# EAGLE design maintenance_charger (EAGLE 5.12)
TP_SIGNAL_NAME: REF
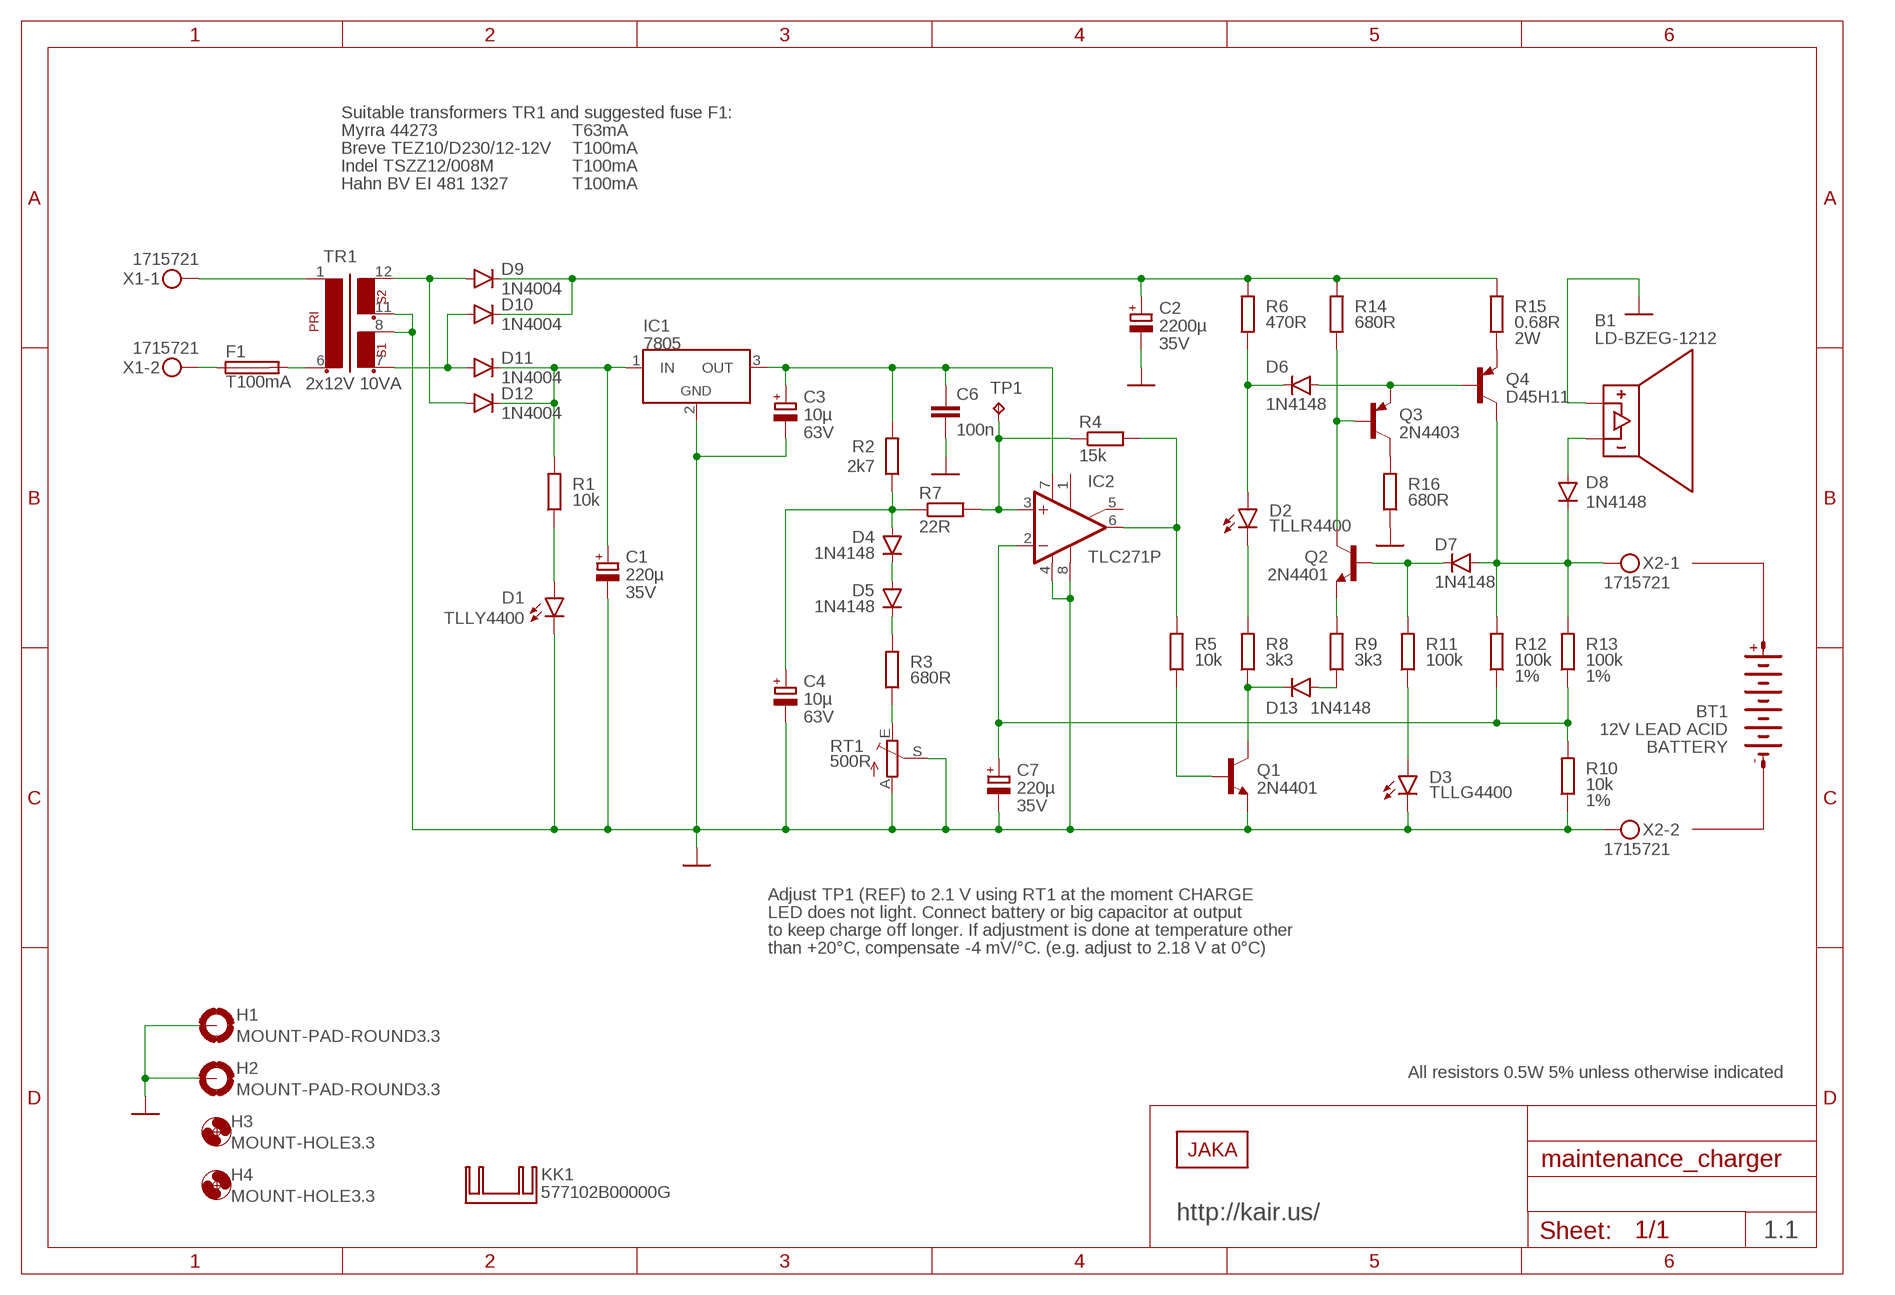
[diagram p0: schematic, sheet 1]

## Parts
B1  LD-BZEG-1212  [LD-BZEG-1212]
C1  220µ  CPOL-EUE3.5-8  [E3,5-8]
C2  2200µ  CPOL-EUE7.5-16  [E7,5-16]
C3  10µ  CPOL-EUE2-5  [E2-5]
C4  10µ  CPOL-EUE2-5  [E2-5]
C6  100n  C-EU050-025X075  [C050-025X075]
C7  220µ  CPOL-EUE3.5-8  [E3,5-8]
D1  TLLY4400  [LED3MM]
D2  TLLR4400  [LED3MM]
D3  TLLG4400  [LED3MM]
D4  1N4148  [DO35-10]
D5  1N4148  [DO35-10]
D6  1N4148  [DO35-10]
D7  1N4148  [DO35-10]
D8  1N4148  [DO35-10]
D9  1N4004  [DO41-10]
D10  1N4004  [DO41-10]
D11  1N4004  [DO41-10]
D12  1N4004  [DO41-10]
D13  1N4148  [DO35-10]
F1  T100mA  TR5  [TR5]
H1  MOUNT-PAD-ROUND3.3  [3,3-PAD]
H2  MOUNT-PAD-ROUND3.3  [3,3-PAD]
H3  MOUNT-HOLE3.3  [3,3]
H4  MOUNT-HOLE3.3  [3,3]
IC1  7805  7805V  [TO220V]
IC2  TLC271P  [DIL08]
KK1  577102B00000G  TO220_HEATSINK  [577102B00000G]
Q1  2N4401  2N4401-NPN-TO92-EBC  [TO92-EBC]
Q2  2N4401  2N4401-NPN-TO92-EBC  [TO92-EBC]
Q3  2N4403  2N4403-PNP-TO92-EBC  [TO92-EBC]
Q4  D45H11  -PNP-TO220  [TO220]
R1  10k  R-EU_0207/10  [0207/10]
R2  2k7  R-EU_0207/10  [0207/10]
R3  680R  R-EU_0207/10  [0207/10]
R4  15k  R-EU_0207/10  [0207/10]
R5  10k  R-EU_0207/10  [0207/10]
R6  470R  R-EU_0207/10  [0207/10]
R7  22R  R-EU_0207/10  [0207/10]
R8  3k3  R-EU_0207/10  [0207/10]
R9  3k3  R-EU_0207/10  [0207/10]
R10  10k  R-EU_0207/10  [0207/10]
R11  100k  R-EU_0207/10  [0207/10]
R12  100k  R-EU_0207/10  [0207/10]
R13  100k  R-EU_0207/10  [0207/10]
R14  680R  R-EU_0207/10  [0207/10]
R15  0.68R  R-EU_0613/15  [P0613/15]
R16  680R  R-EU_0207/10  [0207/10]
RT1  500R  R_TRIM_CT6  [CT6]
TP1  TESTPOINTTH_1MM3_ROUND  [P1-13-R]
TR1  2x12V 10VA  EI48-2-MNTHOLES  [EI48-2-MNTHOLES]
U$1  JAKA_LOGO_SILK_NANO  [JAKA_SILK_NANO]
X1  1715721  MKDS1,5/2_SLOT  [MKDS1,5/2-5,08_SLOT]
X2  1715721  MKDS1,5/2-5,08  [MKDS1,5/2-5,08]

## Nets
AC_FUSED [AC]: F1.2 TR1.6
AC_L [AC]: F1.1 X1.2
AC_N [AC]: TR1.1 X1.1
GND [charge]: B1.P(POS) C1.- C2.- C3.- C4.- C6.2 C7.- D1.K D3.K H1.B3,3(MOUNT) H2.B3,3(MOUNT) IC1.2(GND) IC2.4(V-) IC2.8(OPT) Q1.E R10.1 R16.1 RT1.A RT1.S TR1.8 TR1.11 X2.2
N$1 [charge]: C2.+ D9.C D10.C R6.2 R14.2 R15.2
N$2: D1.A R1.1
N$3 [ctrpwr]: C3.+ C6.1 IC1.3(OUT) IC2.7(V+) R2.2
N$4: R3.1 RT1.E
N$5: D5.C R3.2
N$6: D4.C D5.A
N$7: C4.+ D4.A R2.1 R7.1
N$8: IC2.3(+IN) R4.1 R7.2 TP1.TP
N$9: IC2.6(OUT) R4.2 R5.2
N$10: Q1.B R5.1
N$11: D13.C Q1.C R8.1
N$12 [charge]: D10.A D11.A TR1.7
N$13: Q2.E R9.2
N$14: D2.A D6.C R6.1
N$15: D2.K R8.2
N$16: D7.C Q2.B R11.2
N$17: B1.N(NEG) D8.A
N$18 [charge]: D7.A D8.C Q4.110(C) R12.2 R13.2 X2.1
N$19: D3.A R11.1
N$20: C7.+ IC2.2(-IN) R10.2 R12.1 R13.1
N$21 [charge]: D9.A D12.A TR1.12
N$22 [charge]: Q4.120(E) R15.1
N$23: Q2.C Q3.B R14.1
N$24 [charge]: C1.+ D11.C D12.C IC1.1(IN) R1.2
N$25: D6.A Q3.E Q4.100(B)
N$26: D13.A R9.1
N$27: Q3.C R16.2
Unconnected: IC2.1(ON1) IC2.5(ON2)

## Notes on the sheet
- Suitable transformers TR1 and suggested fuse F1:
- Myrra 44273 | T63mA
- Breve TEZ10/D230/12-12V | T100mA
- Indel TSZZ12/008M | T100mA
- Hahn BV EI 481 1327 | T100mA
- 2W
- 35V
- 63V
- 35V
- 1% | 1%
- 63V
- BATTERY
- 1%
- 35V
- Adjust TP1 (REF) to 2.1 V using RT1 at the moment CHARGE
- LED does not light. Connect battery or big capacitor at output
- to keep charge off longer. If adjustment is done at temperature other
- than +20°C, compensate -4 mV/°C. (e.g. adjust to 2.18 V at 0°C)
- All resistors 0.5W 5% unless otherwise indicated
- http://kair.us/
- 1.1

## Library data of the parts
B1 = omat:LD-BZEG-1212
C1-C4 C7 = omat:CPOL-EU: POLARIZED CAPACITOR, European symbol
C6 = omat:C-EU: CAPACITOR, European symbol
D1 = omat:TLLY4400: Low Current (2mA) LED 3 mm Tinted Diffused Package color YELLOW; MF: VISHAY SEMICONDUCTOR; OC_FARNELL: 1612439
D2 = omat:TLLR4400: Low Current (2mA) LED 3 mm Tinted Diffused Package color RED; MF: VISHAY SEMICONDUCTOR; OC_FARNELL: 1612437
D3 = omat:TLLG4400: Low Current (2mA) LED 3 mm Tinted Diffused Package color GREEN; MF: VISHAY SEMICONDUCTOR; OC_FARNELL: 1612435
D4-D8 D13 = omat:1N4148: DIODE
D9-D12 = omat:1N4004: DIODE
F1 = omat:TR5: FUSE; OC_FARNELL: unknown; OC_NEWARK: unknown
H1 H2 = omat:MOUNT-PAD-ROUND: MOUNTING PAD, round
H3 H4 = omat:MOUNT-HOLE: MOUNTING HOLE with drill center marker
IC1 = omat:7805
IC2 = omat:TLC271
KK1 = omat:TO220_HEATSINK: HEATSINK
Q1 Q2 = omat:*-NPN-: NPN Transistror
Q3 Q4 = omat:*-PNP-: PNP Transistror
R1-R16 = omat:R-EU_: RESISTOR, European symbol
RT1 = omat:R_TRIM_CT6: Copal CT6(E)P single turn trimmer. Also many others fit (SR Passives T75P, Bourns 3362P, Vishay T73YP series). Usually 100 ppm/C, 0.25...0.5W, 250 V
TP1 = omat:TESTPOINT
TR1 = omat:EI48-2: TRANSFORMER 1 primary winding, 2 secondary windings 10 VA typ. E.g.: Indel TSZZ12 Hahn BVEI481 Breve Tufvassons TEZ10 Block EI 48 Myrra EI 48-16,8; DESCRIPTION: TRANSFORMER 2x12V 10VA EI48-2; TMEPARTNO: MYRRA-44273
U$1 = omat:JAKA_LOGO
X1 X2 = omat:MKDS1,5/2: MKDS 1,5/ 2-5,08 Printklemme

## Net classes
0 default: width 0.4 mm, clearance 0.3 mm
1 AC: width 1.5 mm, clearance 5 mm to class 0, clearance 1 mm
2 charge: width 1 mm, clearance 0.5 mm to class 0, clearance 15 mm to class 1, clearance 0.5 mm
3 ctrpwr: width 0.5 mm, clearance 0.3 mm to class 0, clearance 15 mm to class 1, clearance 0.3 mm to class 2, clearance 0.3 mm

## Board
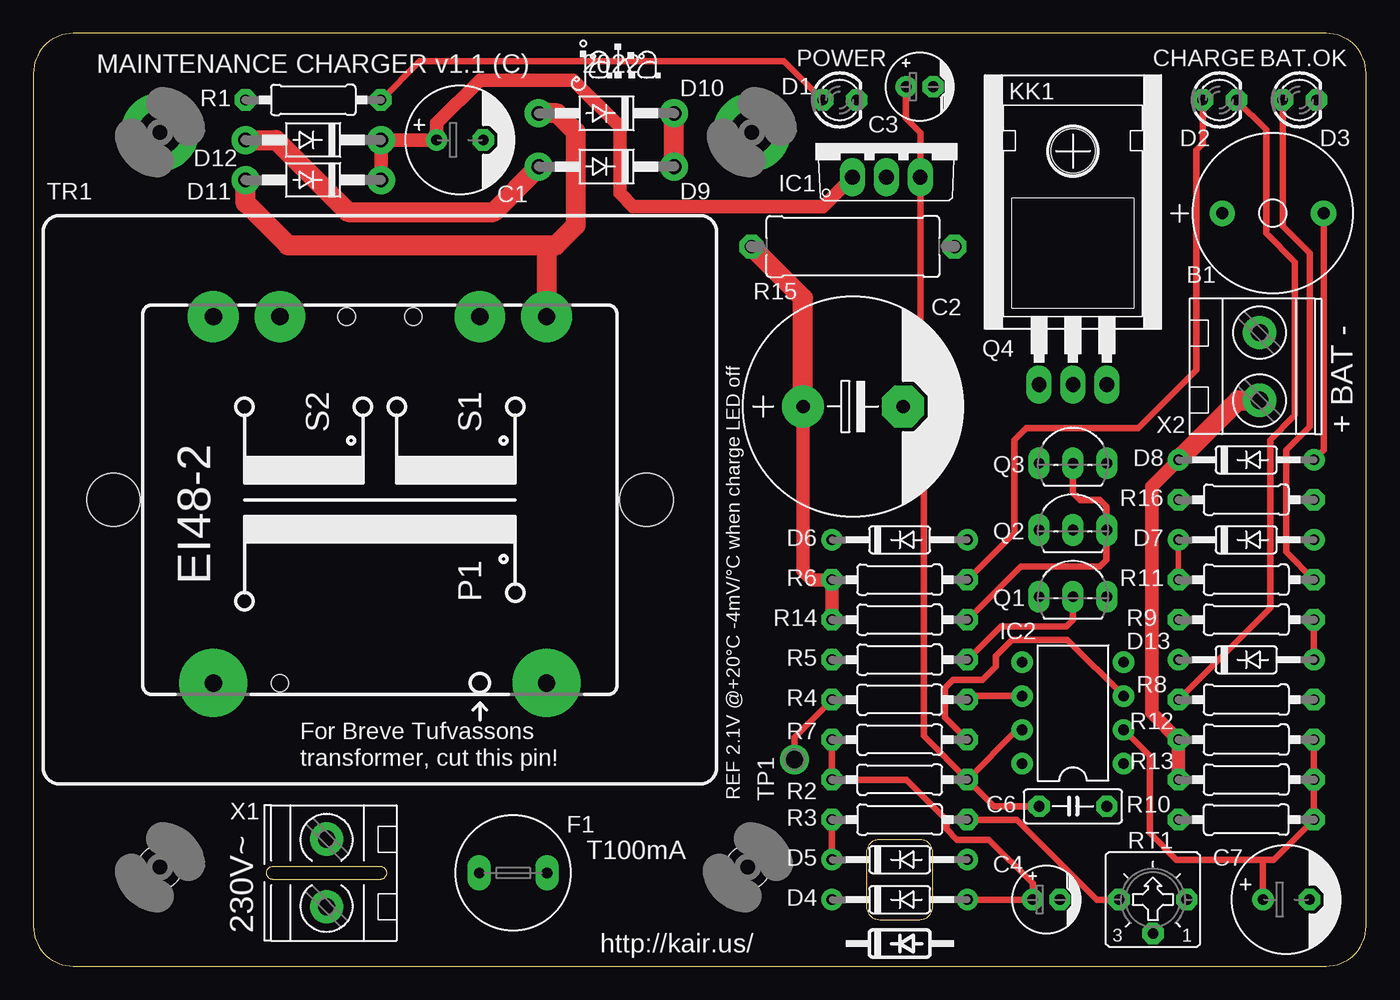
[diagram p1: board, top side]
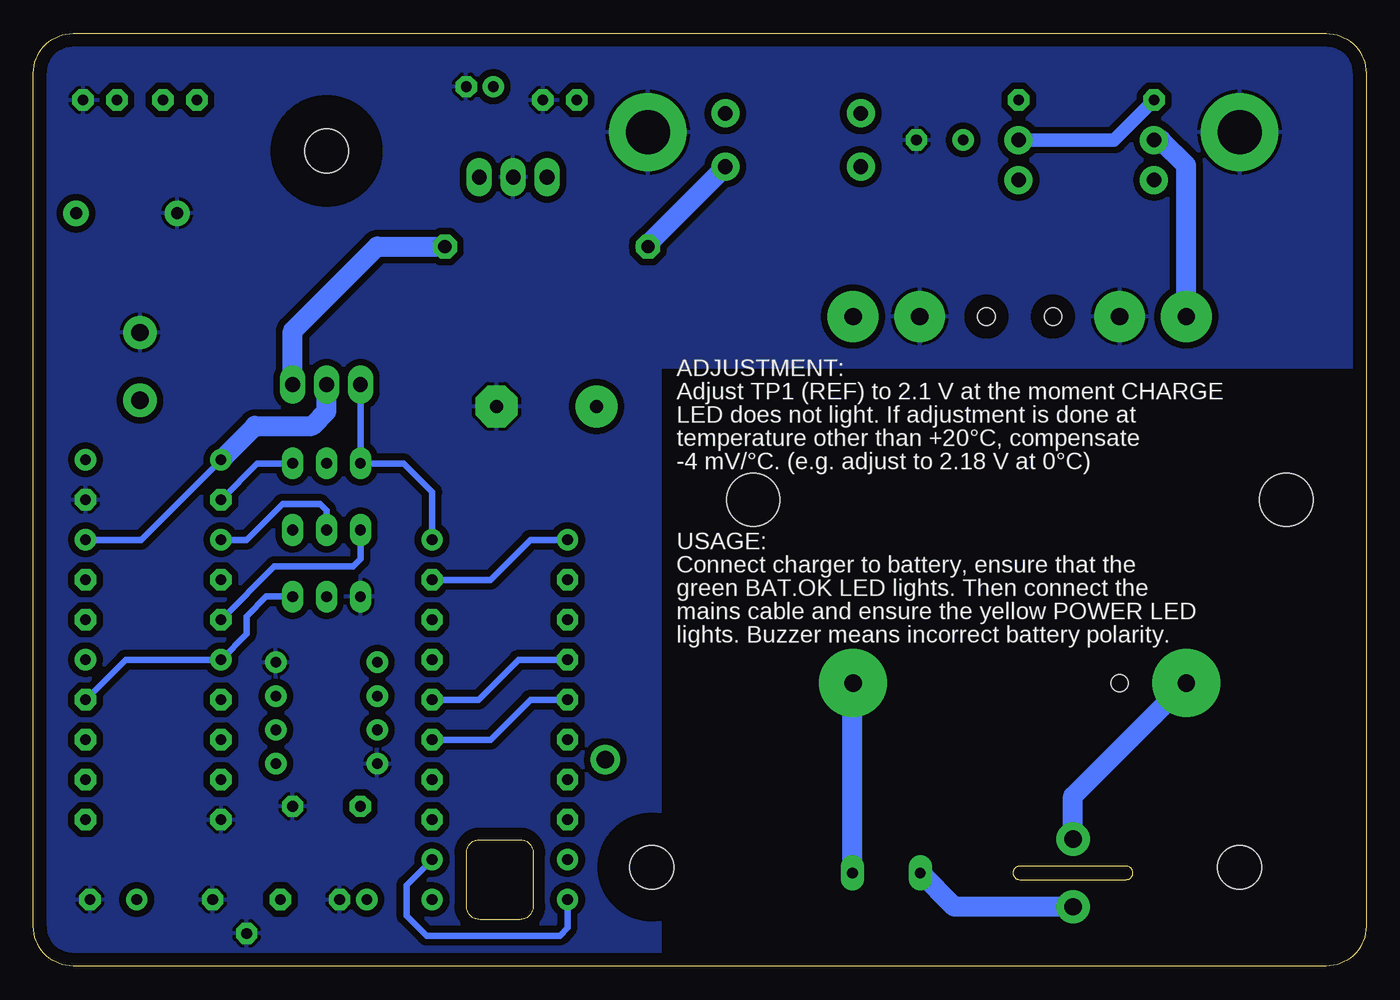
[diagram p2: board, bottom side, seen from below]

Size 100 x 70 mm. Coordinates in mm from the lower left corner, seen from the top.
Outline: 100,67 arc90 97,70 3,70 arc90 0,67 0,3 arc90 3,0 97,0 arc90 100,3 100,67
Copper layers (1*16): Top 0.035mm / dielectric 1.5mm / Bottom 0.035mm
Design rules "default *": minimum track width 0.3mm, minimum drill 0.6mm, track to track 0.3mm, track to pad 0.3mm, pad to pad 0.3mm, via to via 0.3mm, smd to smd 8mil, copper to edge 1mm, drill to drill 0.3mm, minimum pad ring 0.4mm, minimum via ring 0.4mm, stop-mask expansion 4mil, vias tented up to drill 0mil, thermal gap 10mil
bRestrict: area 62.5,3.5 to 67.5,9.5
Milling: 8 lines

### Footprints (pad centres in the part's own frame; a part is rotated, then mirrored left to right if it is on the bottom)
LD-BZEG-1212 = drill 0.9 pad 1.9 round: N 3.8,0; P -3.8,0
E3,5-8 = drill 0.8 pad 1.6 round: + -1.75,0 | drill 0.8 pad 1.6 octagon: - 1.75,0
E7,5-16 = drill 1 pad 3.15 round: + -3.75,0 | drill 1 pad 3.15 octagon: - 3.75,0
E2-5 = drill 0.8 pad 1.27 round: + -1.016,0 | drill 0.8 pad 1.27 octagon: - 1.016,0
C050-025X075 = drill 0.8 octagon: 1 -2.54,0; 2 2.54,0
LED3MM = drill 0.8 octagon: A -1.27,0; K 1.27,0
DO35-10 = drill 0.8 round: A 5.08,0; C -5.08,0
DO41-10 = drill 1.1 pad 2.1 round: A 5.08,0; C -5.08,0
TR5 = drill 0.8 pad 1.778 long: 1 -2.54,0; 2 2.54,0
3,3-PAD = drill 3.3 pad 5.842 round: B3,3 0,0
3,3 = hole 3.3: 0,0
TO220V = drill 1.1 long: 1 -2.54,-2.54; 2 0,-2.54; 3 2.54,-2.54
DIL08 = drill 0.8 pad 1.27 round: 1 -3.81,-3.81; 2 -1.27,-3.81; 3 1.27,-3.81; 4 3.81,-3.81; 5 3.81,3.81; 6 1.27,3.81; 7 -1.27,3.81; 8 -3.81,3.81
TO92-EBC = drill 0.8 long: B 0,-1.27; C 2.54,-1.27; E -2.54,-1.27
TO220 = drill 1.1 long: 100 -2.54,-6.35; 110 0,-6.35; 120 2.54,-6.35 | hole 3.3: 0,11.176
0207/10 = drill 0.8 octagon: 1 -5.08,0; 2 5.08,0
P0613/15 = drill 1 octagon: 1 -7.62,0; 2 7.62,0
CT6 = drill 0.8 octagon: A 2.54,0; E -2.54,0; S 0,-2.54
P1-13-R = drill 1.3 pad 2.2 round: TP 0,0
EI48-2-MNTHOLES = drill 1.3 pad 5.08 round: 1 -13.75,12.5; 6 -13.75,-12.5 | drill 1.3 pad 3.81 round: 7 13.75,-12.5; 8 13.75,-7.5; 11 13.75,7.5; 12 13.75,12.5 | hole 1.3: 13.75,2.5; 13.75,-2.5; -13.75,7.5 | hole 4: 0,-20; 0,20
MKDS1,5/2-5,08_SLOT = drill 1.3 pad 2.5 round: 1 -2.54,0; 2 2.54,0
MKDS1,5/2-5,08 = drill 1.3 pad 2.5 round: 1 -2.54,0; 2 2.54,0

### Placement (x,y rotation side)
B1  93,56.5 0 top
C1  32,62 0 top
C2  61.5,42 0 top
C3  66.5,66 0 top
C4  76,5 0 top
C6  78,12 0 top
C7  94,5 0 top
D1  60.5,65 0 top
D2  89,65 0 top
D3  95,65 0 top
D4  65,5 0 top
D5  65,8 0 top
D6  65,32 0 top
D7  91,32 0 top
D8  91,38 0 top
D9  43,60 180 top
D10  43,64 180 top
D11  21,59 180 top
D12  21,62 180 top
D13  91,23 0 top
F1  36,7 0 top
H1  53.9,62.58 0 top
H2  9.5,62.58 0 top
H3  53.6,7.42 0 top
H4  9.5,7.42 0 top
IC1  64,61.75 0 top
IC2  78,19 90 top
KK1  78,57.35 270 top
Q1  78,29 0 top
Q2  78,34 0 top
Q3  78,39 0 top
Q4  78,50 0 top
R1  21,65 180 top
R2  65,14 0 top
R3  65,11 180 top
R4  65,20 0 top
R5  65,23 180 top
R6  65,29 180 top
R7  65,17 0 top
R8  91,20 180 top
R9  91,26 180 top
R10  91,11 0 top
R11  91,29 180 top
R12  91,17 180 top
R13  91,14 180 top
R14  65,26 180 top
R15  61.5,54 180 top
R16  91,35 180 top
RT1  84,5 0 top
TP1  57.1,15.5 0 top
TR1  26,35 90 top
U$1  43.7,67.6 0 top
X1  22,7 270 top
X2  92,45 90 top

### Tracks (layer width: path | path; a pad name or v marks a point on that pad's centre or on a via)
AC_FUSED
  Bottom 1.5: F1.2 38.54,21.21 TR1.6
AC_L
  Bottom 1.5: X1.2 30.92,4.46 F1.1
AC_N
  Bottom 1.5: TR1.1 22,12.75 X1.1
GND
  pour Bottom: 0,45 0,67 arc-90 3,70 27,70 97,70 arc-90 100,67 100,9 100,3 arc-90 97,0 84,0 53,0 53,45
N$1
  Top 1: R14.2 R6.2 58.4,29 57.75,29.65 C2.+
  Top 1.5: C2.+ 57.75,50.13 R15.2 | D9.C D10.C
  Bottom 1.5: R15.2 54.08,54 D9.C
N$2
  Top 0.5: R1.1 28.98,67.9 56.33,67.9 D1.A
N$3
  Top 0.5: C3.+ 65.48,63.62 66.54,62.56 IC1.3 66.54,46.06 68.8,43.8 68.8,40.1 66.8,38.1 66.8,17.28 R2.2 | C6.1 72.08,12 R2.2 | IC2.7 73.81,17.73 R2.2
N$4
  Top 0.5: R3.1 73.8,11 79.8,5 RT1.E
N$5
  Top 0.5: D5.C R3.2
N$6
  Bottom 0.5: D4.C 59.92,2.88 60.5,2.3 70.5,2.3 72,3.8 72,6.08 D5.A
N$7
  Top 0.5: D4.A C4.+ 74.98,6.22 71.7,9.5 69.3,9.5 68.5,10.3 68.5,11 65.5,14 R2.1 R7.1
N$8
  Top 0.5: R7.2 68.4,18.68 68.4,20.9 69,21.5 71.2,21.5 72.2,22.5 72.2,23.3 73.4,24.5 77.58,24.5 IC2.3 | TP1.TP 57.1,17.18 R4.1
  Bottom 0.5: R4.1 62.7,20 65.7,17 R7.2
N$9
  Top 0.5: R4.2 70.35,20.27 IC2.6
  Bottom 0.5: R5.2 63.6,23 66.6,20 R4.2
N$10
  Top 0.5: R5.1 72.58,25.5 77.5,25.5 78,26 Q1.B
N$11
  Bottom 0.5: Q1.C 82.52,27.73 84,26.25 84,24.92 D13.C 93.08,23 R8.1
N$12
  Top 1.5: D11.A 15.92,57.28 19.1,54.1 38.5,54.1 | 38.5,54.1 39.2,54.1 40.7,55.6 40.7,62.6 39.3,64 D10.A | 38.5,54.1 TR1.7
N$13
  Bottom 0.5: R9.2 81.92,30 76,30 75.46,30.54 Q2.E
N$14
  Top 0.5: R6.1 73.6,32.52 73.6,39.5 74.5,40.4 82.9,40.4 87.25,44.75 87.25,61.25 87.73,61.73 D2.A
  Bottom 0.5: D6.C 62.7,32 65.7,29 R6.1
N$15
  Top 0.5: R8.2 92.8,26.88 92.8,39.5 94.65,41.35 94.65,52.85 92.5,55 92.5,62.77 D2.K
N$16
  Top 0.4: D7.C R11.2
  Bottom 0.5: Q2.B 78,34.2 78.5,34.7 81.3,34.7 84,32 D7.C
N$17
  Top 0.5: B1.N 96.8,38.72 D8.A
N$18
  Top 1: R13.2 R12.2 83.9,19.02 83.9,35.98 D8.C
  Top 1.5: D8.C 90.38,42.46 X2.1
  Bottom 0.5: D7.A 91.92,32 D8.C
  Bottom 1.5: Q4.110 78,41.65 79.1,40.55 83.37,40.55 D8.C
N$19
  Top 0.5: R11.1 94,31.08 94,38.75 95.75,40.5 95.75,53.5 93.73,55.52 D3.A
N$20
  Top 0.5: R10.2 96.08,13.5 | R12.1 R13.1 R10.2 | IC2.2 83.75,15.79 83.75,10 85.75,8 92.25,8 | 92.25,8 93.08,8 R10.2 | 92.25,8 C7.+
N$21
  Top 1.5: D12.A 18.2,62 23.6,56.6 34.52,56.6 D9.A
  Bottom 1.5: TR1.12 13.5,60.1 15.4,62 D12.A
N$22
  Bottom 1.5: R15.1 74.2,54 80.54,47.66 Q4.120
N$23
  Top 0.5: R14.1 74.08,30 80,30 80.5,30.5 80.5,32.69 Q2.C 80.5,32.77 80.5,34.5 80,35 78.5,35 78,35.5 Q3.B
N$24
  Top 1: IC1.1 59.25,57 45,57 44,58 44,63 40.5,66.5 33.5,66.5 30.25,63.25 C1.+ D12.C D11.C
  Bottom 1: R1.2 18.92,62 D12.C
N$25
  Bottom 0.5: Q4.100 Q3.E 72.23,37.73 70.08,35.58 D6.A
N$26
  Top 0.5: D13.A R9.1
N$27
  Bottom 0.5: Q3.C 83.19,37.73 R16.2

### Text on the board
tPlace: POWER | CHARGE | BAT.OK | MAINTENANCE CHARGER v1.1 (C) 2022 | + BAT - | For Breve Tufvassons | transformer, cut this pin! | REF 2.1V @+20°C -4mV/°C when charge LED off | T100mA | 230V~ | http://kair.us/
bNames: ADJUSTMENT: | Adjust TP1 (REF) to 2.1 V at the moment CHARGE | LED does not light. If adjustment is done at | temperature other than +20°C, compensate | -4 mV/°C. (e.g. adjust to 2.18 V at 0°C) | USAGE: | Connect charger to battery, ensure that the | green BAT.OK LED lights. Then connect the | mains cable and ensure the yellow POWER LED | lights. Buzzer means incorrect battery polarity.
_tsilk: POWER | CHARGE | BAT.OK | MAINTENANCE CHARGER v1.1 (C) 2022 | D10 | D1 | KK1 | R1 | C3 | D2 | D3 | D12 | TR1 | D11 | D9 | IC1 | C1 | B1 | R15 | C2 | Q4 | S2 | S1 | X2 | + BAT - | D8 | Q3 | R16 | D6 | Q2 | D7 | EI48-2 | R6 | R11 | P1 | Q1 | R14 | R9 | IC2 | D13 | R5 | R4 | R8 | R12 | For Breve Tufvassons | R7 | REF | transformer, cut this pin! | R13 | REF 2.1V @+20°C -4mV/°C when charge LED off | TP1 | R2 | C6 | R10 | X1 | F1 | R3 | RT1 | T100mA | D5 | C7 | C4 | D4 | 230V~ | 3 | 1 | http://kair.us/
_bsilk: ADJUSTMENT: | Adjust TP1 (REF) to 2.1 V at the moment CHARGE | LED does not light. If adjustment is done at | temperature other than +20°C, compensate | -4 mV/°C. (e.g. adjust to 2.18 V at 0°C) | USAGE: | Connect charger to battery, ensure that the | green BAT.OK LED lights. Then connect the | mains cable and ensure the yellow POWER LED | lights. Buzzer means incorrect battery polarity.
